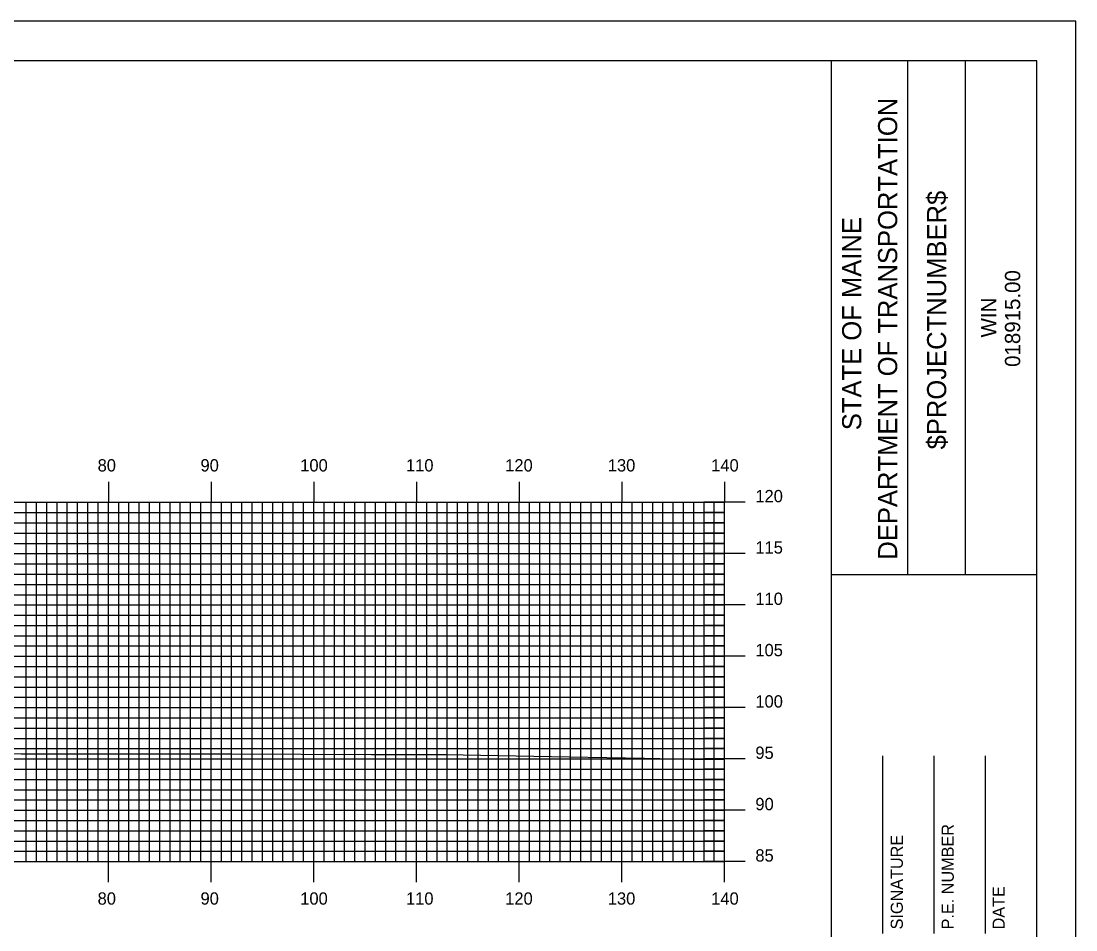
# Model space of a CAD drawing. Extents: x 1786582 to 1786926, y 442591 to 442811.
# Drawn here: x 1786819.6 to 1786922.3, y 442722 to 442810.5 of the extents above; entities that cross this region are included whole.
import ezdxf

# ---------------------------------------------------------------- set-up
doc = ezdxf.new("R2010")
doc.units = 0
for name, color, linetype in [('BORDER', 7, 'Continuous'), ('H_V ANNOTATION', 7, 'Continuous'), ('MAJOR', 7, 'Continuous'), ('MINOR', 7, 'Continuous'), ('PLOT BOUNDARY', 7, 'Continuous'), ('S_Roadway_Centerline', 7, 'Continuous')]:
    doc.layers.add(name, color=color, linetype=linetype)

msp = doc.modelspace()

# ---------------------------------------------------------------- linework, layer by layer
at = {"layer": 'BORDER'}
for p, q in [((1786898.48, 442596.67), (1786898.48, 442806.67)), ((1786905.94, 442756.66), (1786905.94, 442806.66)), ((1786911.53, 442756.66), (1786911.53, 442806.66)), ((1786898.48, 442756.65), (1786918.48, 442756.65)), ((1786903.48, 442721.67), (1786903.48, 442738.97)), ((1786908.48, 442721.67), (1786908.48, 442738.97)), ((1786913.48, 442721.67), (1786913.48, 442738.97))]:
    msp.add_line(p, q, dxfattribs=at)
msp.add_lwpolyline([(1786598.48, 442596.67), (1786918.48, 442596.67), (1786918.48, 442806.67), (1786598.48, 442806.67)], close=True, dxfattribs=at)
at = {"layer": 'MAJOR'}
for p, q in [((1786828.08, 442765.67), (1786828.08, 442763.67)), ((1786838.08, 442765.67), (1786838.08, 442763.67)), ((1786848.08, 442765.67), (1786848.08, 442763.67)), ((1786858.08, 442765.67), (1786858.08, 442763.67)), ((1786868.08, 442765.67), (1786868.08, 442763.67)), ((1786878.08, 442765.67), (1786878.08, 442763.67)), ((1786888.08, 442765.67), (1786888.08, 442763.67)), ((1786608.08, 442763.67), (1786888.08, 442763.67)), ((1786608.08, 442763.67), (1786888.08, 442763.67)), ((1786828.08, 442728.67), (1786828.08, 442763.67)), ((1786838.08, 442728.67), (1786838.08, 442763.67)), ((1786848.08, 442728.67), (1786848.08, 442763.67)), ((1786858.08, 442728.67), (1786858.08, 442763.67)), ((1786868.08, 442728.67), (1786868.08, 442763.67)), ((1786878.08, 442728.67), (1786878.08, 442763.67)), ((1786890.08, 442763.67), (1786886.07, 442763.67)), ((1786888.08, 442728.67), (1786888.08, 442763.67)), ((1786888.08, 442728.67), (1786888.08, 442763.67)), ((1786608.08, 442758.67), (1786888.08, 442758.67)), ((1786890.08, 442758.67), (1786886.07, 442758.67)), ((1786608.08, 442753.67), (1786888.08, 442753.67)), ((1786890.08, 442753.67), (1786886.07, 442753.67)), ((1786608.08, 442748.67), (1786888.08, 442748.67)), ((1786890.08, 442748.67), (1786886.07, 442748.67)), ((1786608.08, 442743.67), (1786888.08, 442743.67)), ((1786890.08, 442743.67), (1786886.07, 442743.67)), ((1786608.08, 442738.67), (1786888.08, 442738.67)), ((1786890.08, 442738.67), (1786886.07, 442738.67)), ((1786608.08, 442733.67), (1786888.08, 442733.67)), ((1786890.08, 442733.67), (1786886.07, 442733.67)), ((1786608.08, 442728.67), (1786888.08, 442728.67)), ((1786608.08, 442728.67), (1786888.08, 442728.67)), ((1786828.08, 442726.66), (1786828.08, 442728.67)), ((1786838.08, 442726.66), (1786838.08, 442728.67)), ((1786848.08, 442726.66), (1786848.08, 442728.67)), ((1786858.08, 442726.66), (1786858.08, 442728.67)), ((1786868.08, 442726.66), (1786868.08, 442728.67)), ((1786878.08, 442726.66), (1786878.08, 442728.67)), ((1786890.08, 442728.67), (1786886.07, 442728.67)), ((1786888.08, 442726.66), (1786888.08, 442728.67))]:
    msp.add_line(p, q, dxfattribs=at)
at = {"layer": 'MINOR'}
for p, q in [((1786820.08, 442728.67), (1786820.08, 442763.67)), ((1786821.08, 442728.67), (1786821.08, 442763.67)), ((1786822.08, 442728.67), (1786822.08, 442763.67)), ((1786823.08, 442728.67), (1786823.08, 442763.67)), ((1786824.08, 442728.67), (1786824.08, 442763.67)), ((1786825.08, 442728.67), (1786825.08, 442763.67)), ((1786826.08, 442728.67), (1786826.08, 442763.67)), ((1786827.08, 442728.67), (1786827.08, 442763.67)), ((1786829.08, 442728.67), (1786829.08, 442763.67)), ((1786830.08, 442728.67), (1786830.08, 442763.67)), ((1786831.08, 442728.67), (1786831.08, 442763.67)), ((1786832.08, 442728.67), (1786832.08, 442763.67)), ((1786833.08, 442728.67), (1786833.08, 442763.67)), ((1786834.08, 442728.67), (1786834.08, 442763.67)), ((1786835.08, 442728.67), (1786835.08, 442763.67)), ((1786836.08, 442728.67), (1786836.08, 442763.67)), ((1786837.08, 442728.67), (1786837.08, 442763.67)), ((1786839.08, 442728.67), (1786839.08, 442763.67)), ((1786840.08, 442728.67), (1786840.08, 442763.67)), ((1786841.08, 442728.67), (1786841.08, 442763.67)), ((1786842.08, 442728.67), (1786842.08, 442763.67)), ((1786843.08, 442728.67), (1786843.08, 442763.67)), ((1786844.08, 442728.67), (1786844.08, 442763.67)), ((1786845.08, 442728.67), (1786845.08, 442763.67)), ((1786846.08, 442728.67), (1786846.08, 442763.67)), ((1786847.08, 442728.67), (1786847.08, 442763.67)), ((1786849.08, 442728.67), (1786849.08, 442763.67)), ((1786850.08, 442728.67), (1786850.08, 442763.67)), ((1786851.08, 442728.67), (1786851.08, 442763.67)), ((1786852.08, 442728.67), (1786852.08, 442763.67)), ((1786853.08, 442728.67), (1786853.08, 442763.67)), ((1786854.08, 442728.67), (1786854.08, 442763.67)), ((1786855.08, 442728.67), (1786855.08, 442763.67)), ((1786856.08, 442728.67), (1786856.08, 442763.67)), ((1786857.08, 442728.67), (1786857.08, 442763.67)), ((1786859.08, 442728.67), (1786859.08, 442763.67)), ((1786860.08, 442728.67), (1786860.08, 442763.67)), ((1786861.08, 442728.67), (1786861.08, 442763.67)), ((1786862.08, 442728.67), (1786862.08, 442763.67)), ((1786863.08, 442728.67), (1786863.08, 442763.67)), ((1786864.08, 442728.67), (1786864.08, 442763.67)), ((1786865.08, 442728.67), (1786865.08, 442763.67)), ((1786866.08, 442728.67), (1786866.08, 442763.67)), ((1786867.08, 442728.67), (1786867.08, 442763.67)), ((1786869.08, 442728.67), (1786869.08, 442763.67)), ((1786870.08, 442728.67), (1786870.08, 442763.67)), ((1786871.08, 442728.67), (1786871.08, 442763.67)), ((1786872.08, 442728.67), (1786872.08, 442763.67)), ((1786873.08, 442728.67), (1786873.08, 442763.67)), ((1786874.08, 442728.67), (1786874.08, 442763.67)), ((1786875.08, 442728.67), (1786875.08, 442763.67)), ((1786876.08, 442728.67), (1786876.08, 442763.67)), ((1786877.08, 442728.67), (1786877.08, 442763.67)), ((1786879.08, 442728.67), (1786879.08, 442763.67)), ((1786880.08, 442728.67), (1786880.08, 442763.67)), ((1786881.08, 442728.67), (1786881.08, 442763.67)), ((1786882.08, 442728.67), (1786882.08, 442763.67)), ((1786883.08, 442728.67), (1786883.08, 442763.67)), ((1786884.08, 442728.67), (1786884.08, 442763.67)), ((1786885.08, 442728.67), (1786885.08, 442763.67)), ((1786886.08, 442728.67), (1786886.08, 442763.67)), ((1786887.08, 442728.67), (1786887.08, 442763.67)), ((1786608.08, 442762.67), (1786888.08, 442762.67)), ((1786888.08, 442762.67), (1786886.07, 442762.67)), ((1786608.08, 442761.67), (1786888.08, 442761.67)), ((1786888.08, 442761.67), (1786886.07, 442761.67)), ((1786608.08, 442760.67), (1786888.08, 442760.67)), ((1786888.08, 442760.67), (1786886.07, 442760.67)), ((1786608.08, 442759.67), (1786888.08, 442759.67)), ((1786888.08, 442759.67), (1786886.07, 442759.67)), ((1786608.08, 442757.67), (1786888.08, 442757.67)), ((1786888.08, 442757.67), (1786886.07, 442757.67)), ((1786608.08, 442756.67), (1786888.08, 442756.67)), ((1786888.08, 442756.67), (1786886.07, 442756.67)), ((1786608.08, 442755.67), (1786888.08, 442755.67)), ((1786888.08, 442755.67), (1786886.07, 442755.67)), ((1786608.08, 442754.67), (1786888.08, 442754.67)), ((1786888.08, 442754.67), (1786886.07, 442754.67)), ((1786608.08, 442752.67), (1786888.08, 442752.67)), ((1786888.08, 442752.67), (1786886.07, 442752.67)), ((1786608.08, 442751.67), (1786888.08, 442751.67)), ((1786888.08, 442751.67), (1786886.07, 442751.67)), ((1786608.08, 442750.67), (1786888.08, 442750.67)), ((1786888.08, 442750.67), (1786886.07, 442750.67)), ((1786608.08, 442749.67), (1786888.08, 442749.67)), ((1786888.08, 442749.67), (1786886.07, 442749.67)), ((1786608.08, 442747.67), (1786888.08, 442747.67)), ((1786888.08, 442747.67), (1786886.07, 442747.67)), ((1786608.08, 442746.67), (1786888.08, 442746.67)), ((1786888.08, 442746.67), (1786886.07, 442746.67)), ((1786608.08, 442745.67), (1786888.08, 442745.67)), ((1786888.08, 442745.67), (1786886.07, 442745.67)), ((1786608.08, 442744.67), (1786888.08, 442744.67)), ((1786888.08, 442744.67), (1786886.07, 442744.67)), ((1786608.08, 442742.67), (1786888.08, 442742.67)), ((1786888.08, 442742.67), (1786886.07, 442742.67)), ((1786608.08, 442741.67), (1786888.08, 442741.67)), ((1786888.08, 442741.67), (1786886.07, 442741.67)), ((1786608.08, 442740.67), (1786888.08, 442740.67)), ((1786888.08, 442740.67), (1786886.07, 442740.67)), ((1786608.08, 442739.67), (1786888.08, 442739.67)), ((1786888.08, 442739.67), (1786886.07, 442739.67)), ((1786608.08, 442737.67), (1786888.08, 442737.67)), ((1786888.08, 442737.67), (1786886.07, 442737.67)), ((1786608.08, 442736.67), (1786888.08, 442736.67)), ((1786888.08, 442736.67), (1786886.07, 442736.67)), ((1786608.08, 442735.67), (1786888.08, 442735.67)), ((1786888.08, 442735.67), (1786886.07, 442735.67)), ((1786608.08, 442734.67), (1786888.08, 442734.67)), ((1786888.08, 442734.67), (1786886.07, 442734.67)), ((1786608.08, 442732.67), (1786888.08, 442732.67)), ((1786888.08, 442732.67), (1786886.07, 442732.67)), ((1786608.08, 442731.67), (1786888.08, 442731.67)), ((1786888.08, 442731.67), (1786886.07, 442731.67)), ((1786608.08, 442730.67), (1786888.08, 442730.67)), ((1786888.08, 442730.67), (1786886.07, 442730.67)), ((1786608.08, 442729.67), (1786888.08, 442729.67)), ((1786888.08, 442729.67), (1786886.07, 442729.67))]:
    msp.add_line(p, q, dxfattribs=at)
at = {"layer": 'PLOT BOUNDARY'}
msp.add_lwpolyline([(1786582.29, 442590.55), (1786922.29, 442590.55), (1786922.29, 442810.55), (1786582.29, 442810.55)], close=True, dxfattribs=at)
at = {"layer": 'S_Roadway_Centerline'}
msp.add_lwpolyline([(1786806.24, 442739.25), (1786819.58, 442739.18), (1786825.91, 442739.17), (1786834.57, 442739.17), (1786840.04, 442739.15), (1786853.7, 442739.11), (1786859.99, 442739.09), (1786861.09, 442739.09), (1786862.61, 442739.06), (1786872.96, 442738.86), (1786880.27, 442738.75), (1786884.77, 442738.66), (1786888.08, 442738.66)], dxfattribs=at)

# ---------------------------------------------------------------- texts
at = {"layer": 'BORDER'}
for s, height, p in [('DEPARTMENT OF TRANSPORTATION', 1.8635, (1786904.89, 442758.08)), ('$PROJECTNUMBER$', 1.8635, (1786909.66, 442768.82)), ('STATE OF MAINE', 1.8635, (1786901.39, 442770.69)), ('018915.00', 1.491, (1786916.87, 442776.86)), ('WIN', 1.491, (1786914.55, 442779.73)), ('P.E. NUMBER', 1.1811, (1786910.4, 442722.06)), ('SIGNATURE', 1.181, (1786905.44, 442722.06)), ('DATE', 1.181, (1786915.36, 442722.06))]:
    msp.add_text(s, height=height, rotation=90, dxfattribs=at).set_placement(p)
at = {"layer": 'H_V ANNOTATION'}
for s, p in [('80', (1786827.03, 442766.67)), ('90', (1786837.05, 442766.67)), ('100', (1786846.76, 442766.67)), ('110', (1786857.06, 442766.67)), ('120', (1786866.72, 442766.67)), ('130', (1786876.71, 442766.67)), ('140', (1786886.78, 442766.67)), ('120', (1786891.08, 442763.67)), ('115', (1786891.08, 442758.67)), ('110', (1786891.08, 442753.67)), ('105', (1786891.08, 442748.67)), ('100', (1786891.08, 442743.67)), ('95', (1786891.08, 442738.67)), ('90', (1786891.08, 442733.67)), ('85', (1786891.08, 442728.67)), ('80', (1786827.03, 442724.47)), ('90', (1786837.05, 442724.47)), ('100', (1786846.76, 442724.47)), ('110', (1786857.06, 442724.47)), ('120', (1786866.72, 442724.47)), ('130', (1786876.71, 442724.47)), ('140', (1786886.78, 442724.47))]:
    msp.add_text(s, height=1.2, dxfattribs=at).set_placement(p)

doc.saveas('drawing.dxf')
